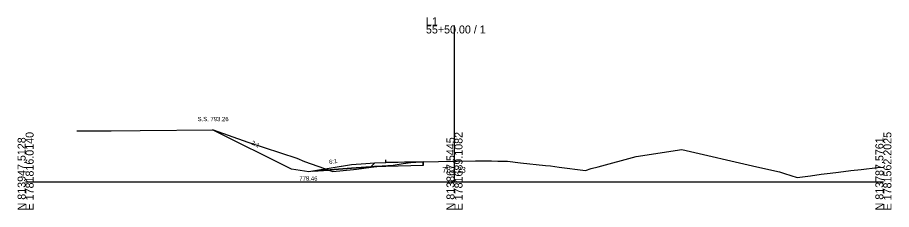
# Model space of a CAD drawing. Extents: x 5574 to 10203, y -10 to 9546.
# Drawn here: x 6597.2 to 6902.8, y 2490.3 to 2557.6 of the extents above; entities that cross this region are included whole.
import ezdxf

# ---------------------------------------------------------------- set-up
doc = ezdxf.new("R2010")
doc.units = 0
for name, color, linetype in [('Exist Cross Section Cell', 7, 'Continuous'), ('Exist XS Center Line Elevation Label', 7, 'Continuous'), ('Exist XS Ground Line', 7, 'Continuous'), ('Prop XS Ditch Slope Text', 7, 'Continuous'), ('Prop XS Ditch Standard Text', 7, 'Continuous'), ('Prop XS Dump Level', 7, 'Continuous'), ('Prop XS Earthwork Shape', 7, 'Continuous'), ('Prop XS EOT Tick Mark', 7, 'Continuous'), ('Prop XS Finish Grade', 7, 'Continuous'), ('Prop XS Finish Grade Earthwork', 7, 'Continuous'), ('Prop XS Finish Grade Paved Shoulder', 7, 'Continuous'), ('Prop XS Finish Grade Pavement', 7, 'Continuous'), ('Prop XS Hydro Typical Ditch Data', 7, 'Continuous'), ('Prop XS Pvmt Edge Slope', 7, 'Continuous'), ('Prop XS Side Slope Text', 7, 'Continuous'), ('Prop XS SS Elevation Text', 7, 'Continuous'), ('Prop XS Subgrade Earthwork', 7, 'Continuous'), ('Scratch_Level_3', 7, 'Continuous'), ('Scratch_Level_6', 7, 'Continuous')]:
    doc.layers.add(name, color=color, linetype=linetype)

msp = doc.modelspace()

# ---------------------------------------------------------------- linework, layer by layer
at = {"layer": 'Exist Cross Section Cell'}
for p, q in [((6750, 2500), (6750, 2554.78)), ((6600, 2500), (6750, 2500)), ((6750, 2500), (6900, 2500))]:
    msp.add_line(p, q, dxfattribs=at)
at = {"layer": 'Exist XS Ground Line'}
for p, q in [((6617.9, 2517.86), (6622.86, 2517.92)), ((6622.86, 2517.92), (6628.51, 2517.83)), ((6628.51, 2517.83), (6629.87, 2517.85)), ((6629.87, 2517.85), (6640.01, 2517.98)), ((6640.01, 2517.98), (6665.57, 2518.26)), ((6665.57, 2518.26), (6677.77, 2513.94)), ((6677.77, 2513.94), (6694.91, 2508.27)), ((6813.53, 2508.91), (6829.53, 2511.34)), ((6829.53, 2511.34), (6855.77, 2505.23)), ((6694.91, 2508.27), (6697.55, 2507.16)), ((6697.55, 2507.16), (6704.59, 2504.71)), ((6731.99, 2506.4), (6734.7, 2506.77)), ((6734.7, 2506.77), (6736.48, 2506.86)), ((6736.48, 2506.86), (6738.98, 2506.98)), ((6738.98, 2506.98), (6744.37, 2507.1)), ((6744.37, 2507.1), (6750, 2507.23)), ((6750, 2507.23), (6750.96, 2507.26)), ((6750.96, 2507.26), (6757.36, 2507.32)), ((6757.36, 2507.32), (6761.91, 2507.37)), ((6761.91, 2507.37), (6762.94, 2507.34)), ((6762.94, 2507.34), (6765.15, 2507.3)), ((6765.15, 2507.3), (6766.68, 2507.25)), ((6766.68, 2507.25), (6768.48, 2507.2)), ((6768.48, 2507.2), (6773.07, 2506.68)), ((6773.07, 2506.68), (6781.8, 2505.75)), ((6800.2, 2505.29), (6813.53, 2508.91)), ((6704.59, 2504.71), (6707.48, 2503.63)), ((6707.48, 2503.63), (6714.62, 2504.33)), ((6714.62, 2504.33), (6715.72, 2504.44)), ((6715.72, 2504.44), (6722.63, 2505.35)), ((6722.63, 2505.35), (6724.74, 2505.56)), ((6724.74, 2505.56), (6728.54, 2505.85)), ((6728.54, 2505.85), (6731.99, 2506.4)), ((6781.8, 2505.75), (6783.55, 2505.61)), ((6783.55, 2505.61), (6786.58, 2505.18)), ((6786.58, 2505.18), (6795.82, 2503.99)), ((6795.82, 2503.99), (6797.84, 2504.67)), ((6797.84, 2504.67), (6800.2, 2505.29)), ((6855.77, 2505.23), (6863.61, 2503.53)), ((6884.34, 2503.42), (6888.61, 2503.93)), ((6888.61, 2503.93), (6892.19, 2504.37)), ((6892.19, 2504.37), (6897.89, 2505.04)), ((6897.89, 2505.04), (6900, 2505.15)), ((6863.61, 2503.53), (6865.39, 2502.92)), ((6865.39, 2502.92), (6869.83, 2501.49)), ((6869.83, 2501.49), (6874.53, 2502.13)), ((6874.53, 2502.13), (6878.25, 2502.69)), ((6878.25, 2502.69), (6881.33, 2503.09)), ((6881.33, 2503.09), (6884.34, 2503.42))]:
    msp.add_line(p, q, dxfattribs=at)
at = {"layer": 'Prop XS Dump Level'}
msp.add_line((6738.99, 2507.01), (6726, 2506.75), dxfattribs=at)
msp.add_line((6738.99, 2507.01), (6726, 2506.75), dxfattribs=at)
at = {"layer": 'Prop XS Earthwork Shape'}
for points in [[(6665.4, 2518.26), (6665.57, 2518.26), (6677.77, 2513.94), (6694.91, 2508.27), (6697.55, 2507.16), (6704.59, 2504.71), (6706.1, 2504.15), (6700.43, 2503.7), (6699, 2503.46), (6693, 2504.46)], [(6726, 2505.44), (6722.78, 2505.37), (6724.74, 2505.56), (6728.54, 2505.85), (6731.99, 2506.4), (6734.7, 2506.77), (6736.48, 2506.86), (6738.99, 2506.98), (6738.99, 2505.73)], [(6714, 2504.78), (6706.1, 2504.15), (6707.48, 2503.63), (6714.62, 2504.33), (6715.72, 2504.44), (6722.63, 2505.35), (6722.78, 2505.37), (6722, 2505.35), (6720.72, 2505.32), (6719, 2505.18)]]:
    msp.add_lwpolyline(points, close=True, dxfattribs=at)
at = {"layer": 'Prop XS EOT Tick Mark'}
msp.add_line((6726, 2506.69), (6726, 2507.69), dxfattribs=at)
at = {"layer": 'Prop XS Finish Grade'}
for p, q in [((6722, 2506.6), (6719, 2506.36)), ((6714, 2505.96), (6700.43, 2503.7)), ((6719, 2506.36), (6714, 2505.96))]:
    msp.add_line(p, q, dxfattribs=at)
at = {"layer": 'Prop XS Finish Grade Earthwork'}
for p, q in [((6693, 2504.46), (6665.4, 2518.26)), ((6699, 2503.46), (6693, 2504.46)), ((6700.43, 2503.7), (6699, 2503.46))]:
    msp.add_line(p, q, dxfattribs=at)
at = {"layer": 'Prop XS Finish Grade Paved Shoulder'}
msp.add_line((6726, 2506.69), (6722, 2506.6), dxfattribs=at)
at = {"layer": 'Prop XS Finish Grade Pavement'}
msp.add_line((6738.99, 2506.98), (6726, 2506.69), dxfattribs=at)
at = {"layer": 'Prop XS Hydro Typical Ditch Data'}
for p, q in [((6693, 2504.46), (6665.4, 2518.26)), ((6699, 2503.46), (6693, 2504.46)), ((6714, 2505.96), (6699, 2503.46))]:
    msp.add_line(p, q, dxfattribs=at)
at = {"layer": 'Prop XS Pvmt Edge Slope'}
msp.add_line((6722, 2506.6), (6720.72, 2505.32), dxfattribs=at)
at = {"layer": 'Prop XS Subgrade Earthwork'}
for p, q in [((6738.99, 2505.73), (6738.99, 2506.98)), ((6714, 2504.78), (6700.43, 2503.7)), ((6719, 2505.18), (6714, 2504.78)), ((6720.72, 2505.32), (6719, 2505.18)), ((6722, 2505.35), (6720.72, 2505.32)), ((6726, 2505.44), (6722, 2505.35)), ((6738.99, 2505.73), (6726, 2505.44))]:
    msp.add_line(p, q, dxfattribs=at)
at = {"layer": 'Scratch_Level_3'}
for p, q in [((6722, 2506.6), (6719, 2506.36)), ((6720.72, 2505.32), (6722, 2506.6)), ((6714, 2505.96), (6700.43, 2503.7)), ((6700.43, 2503.7), (6714, 2504.78)), ((6719, 2506.36), (6714, 2505.96)), ((6714, 2504.78), (6719, 2505.18)), ((6719, 2505.18), (6720.72, 2505.32))]:
    msp.add_line(p, q, dxfattribs=at)
at = {"layer": 'Scratch_Level_6'}
for points in [[(6726, 2505.44), (6722.78, 2505.37), (6724.74, 2505.56), (6728.54, 2505.85), (6731.99, 2506.4), (6734.7, 2506.77), (6736.48, 2506.86), (6738.99, 2506.98), (6738.99, 2505.73)], [(6705.19, 2504.49), (6700.43, 2503.7), (6706.1, 2504.15)]]:
    msp.add_lwpolyline(points, close=True, dxfattribs=at)

# ---------------------------------------------------------------- texts
at = {"layer": 'Exist Cross Section Cell'}
for s, p in [('L1', (6740, 2554.78)), ('55+50.00 / 1', (6740, 2551.98))]:
    msp.add_text(s, height=2.8, dxfattribs=at).set_placement(p)
for s, p in [('E 1781816.0140', (6602.8, 2490)), ('E 1781689.1082', (6752.8, 2490)), ('E 1781562.2025', (6902.8, 2490)), ('N 813947.5128', (6600, 2490)), ('N 813867.5445', (6750, 2490)), ('N 813787.5761', (6900, 2490))]:
    msp.add_text(s, height=2.8, rotation=90, dxfattribs=at).set_placement(p)
at = {"layer": 'Exist XS Center Line Elevation Label'}
msp.add_text('782.23', height=2, dxfattribs=at).set_placement((6745.75, 2503.23))
at = {"layer": 'Prop XS Ditch Slope Text'}
msp.add_text('6:1', height=1.5, rotation=9.4623, dxfattribs=at).set_placement((6706.25, 2506.19))
at = {"layer": 'Prop XS Ditch Standard Text'}
msp.add_text('778.46', height=1.5, dxfattribs=at).set_placement((6695.74, 2500.46))
at = {"layer": 'Prop XS Dump Level'}
for s, height, p in [('Eop', 0.3, (6738.99, 2506.68)), ('Case4', 0.04, (6714, 2505.92))]:
    msp.add_text(s, height=height, dxfattribs=at).set_placement(p)
at = {"layer": 'Prop XS Side Slope Text'}
msp.add_text('2:1', height=1.5, rotation=333.4349, dxfattribs=at).set_placement((6678.79, 2513.24))
at = {"layer": 'Prop XS SS Elevation Text'}
msp.add_text('S.S. 793.26', height=1.5, dxfattribs=at).set_placement((6660.17, 2521.26))

doc.saveas('drawing.dxf')
